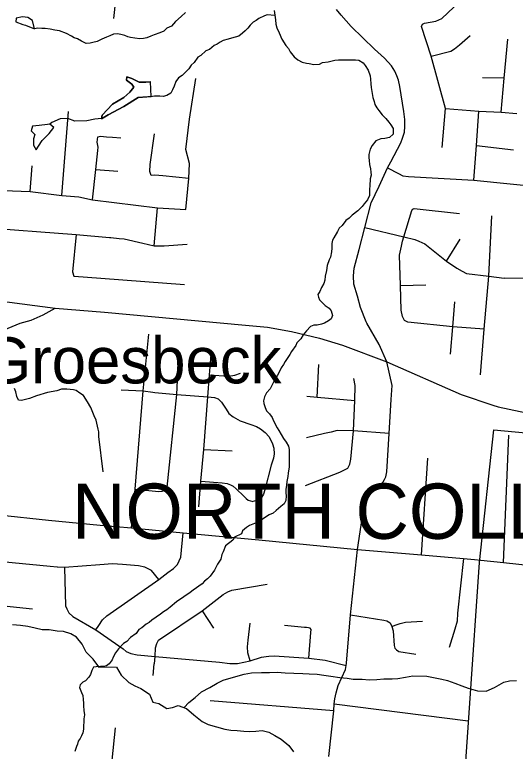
# Model space of a CAD drawing. Extents: x 0 to 34, y 0 to 22.
# Drawn here: x 4.564 to 5.421, y 15.023 to 16.285 of the extents above; entities that cross this region are included whole.
import ezdxf

# ---------------------------------------------------------------- set-up
doc = ezdxf.new("R2010")
doc.units = 0
for name, color, linetype in [('GM_X_City_Street', 7, 'Continuous'), ('GM_X_Corporation', 7, 'Continuous'), ('GM_X_Corporation_Text', 7, 'Continuous'), ('GM_X_County_Road', 7, 'Continuous'), ('GM_X_Minor_Lake', 7, 'Continuous'), ('GM_X_Minor_River', 7, 'Continuous'), ('GM_X_State_Route', 7, 'Continuous'), ('GM_X_Township_Subdivision', 7, 'Continuous'), ('GM_X_Unincorporated_Text', 7, 'Continuous')]:
    doc.layers.add(name, color=color, linetype=linetype)

msp = doc.modelspace()

# ---------------------------------------------------------------- linework, layer by layer
at = {"layer": 'GM_X_City_Street'}
for points in [[(5.4006, 15.3461), (5.41, 15.5645)], [(5.351, 15.3514), (5.3619, 15.3502), (5.4006, 15.3461), (5.5108, 15.3345)]]:
    msp.add_lwpolyline(points, dxfattribs=at)
at = {"layer": 'GM_X_Corporation'}
msp.add_lwpolyline([(5.3269, 14.8644), (5.36, 15.3466), (5.3844, 15.5735), (5.5787, 15.5551), (5.5807, 15.5674), (5.8665, 15.5358), (5.8686, 15.5537), (5.9354, 15.5498), (5.9645, 15.8066), (5.9702, 15.8563), (6.4625, 15.7812), (6.9592, 15.6968), (6.9605, 15.6641), (7.1222, 15.6381)], dxfattribs=at)
at = {"layer": 'GM_X_County_Road'}
for points in [[(5.1657, 15.7589), (5.1559, 15.7831), (5.151, 15.8025), (5.1444, 15.8229), (5.1438, 15.8374), (5.1451, 15.8507), (5.1538, 15.8827), (5.1633, 15.9201), (5.174, 15.9624), (5.1809, 15.977), (5.188, 15.9913), (5.2022, 16.0226), (5.2078, 16.0328), (5.2193, 16.0543), (5.2248, 16.0653), (5.2281, 16.0731), (5.2314, 16.0834), (5.2321, 16.093), (5.2317, 16.1054), (5.2299, 16.1191), (5.2233, 16.1615), (5.2208, 16.1726), (5.2183, 16.1803), (5.215, 16.1881), (5.2089, 16.197), (5.1971, 16.2101), (5.1802, 16.2256), (5.1401, 16.2646), (5.1231, 16.2839), (5.1147, 16.2938)], [(5.2087, 15.6258), (5.2102, 15.6493), (5.201, 15.6901), (5.1882, 15.72), (5.1668, 15.7562), (5.1657, 15.7589)], [(5.1017, 15.0142), (5.1101, 15.0924), (5.1111, 15.1045), (5.1121, 15.113), (5.1142, 15.1228), (5.118, 15.1354), (5.1303, 15.1632), (5.1312, 15.1697), (5.1319, 15.1738), (5.139, 15.2568), (5.1507, 15.3687), (5.1604, 15.4332), (5.1638, 15.4483), (5.1657, 15.4549), (5.1685, 15.46), (5.1713, 15.4638), (5.1744, 15.4669), (5.1856, 15.4753), (5.1903, 15.4797), (5.1949, 15.4845), (5.1972, 15.4886), (5.1991, 15.4932), (5.2012, 15.5016), (5.2049, 15.5671), (5.2087, 15.6258)], [(4.5333, 15.4281), (4.5365, 15.4278), (4.6218, 15.4186), (4.7103, 15.4103), (4.7637, 15.4056), (4.8525, 15.397), (4.9822, 15.3853), (5.1507, 15.3687)], [(5.1507, 15.3687), (5.2604, 15.3597), (5.3321, 15.3534), (5.351, 15.3514)]]:
    msp.add_lwpolyline(points, dxfattribs=at)
at = {"layer": 'GM_X_Minor_Lake'}
for points in [[(4.5981, 16.2605), (4.5946, 16.2751), (4.5863, 16.2802), (4.5773, 16.2812), (4.5662, 16.2788), (4.5657, 16.2724), (4.5781, 16.2679), (4.5826, 16.2667)], [(4.5826, 16.2667), (4.5981, 16.2605)], [(4.7965, 16.1699), (4.7882, 16.169), (4.7772, 16.1693), (4.7644, 16.1756), (4.7558, 16.1785), (4.7556, 16.1728), (4.7646, 16.1658), (4.7679, 16.1604), (4.7612, 16.1522), (4.7508, 16.1429), (4.7315, 16.1316), (4.7136, 16.1126), (4.7127, 16.1065), (4.7239, 16.1131), (4.7508, 16.1277), (4.7751, 16.1431), (4.7978, 16.1446)], [(4.7998, 16.1447), (4.7751, 16.1431), (4.7508, 16.1277), (4.7239, 16.1131), (4.7127, 16.1065), (4.7136, 16.1126), (4.7315, 16.1316), (4.7508, 16.1429), (4.7612, 16.1522), (4.7679, 16.1604), (4.7646, 16.1658), (4.7556, 16.1728), (4.7558, 16.1785), (4.7644, 16.1756), (4.7772, 16.1693), (4.7882, 16.169), (4.797, 16.17)], [(4.7978, 16.1446), (4.7965, 16.1699)], [(4.6199, 16.0964), (4.6061, 16.0948), (4.5947, 16.0936), (4.5923, 16.086), (4.5982, 16.0798), (4.5961, 16.0723), (4.5959, 16.0613), (4.601, 16.0532), (4.6046, 16.0595), (4.6109, 16.0693), (4.6229, 16.0812), (4.6308, 16.0916), (4.624, 16.0971)], [(4.624, 16.0971), (4.6199, 16.0964)]]:
    msp.add_lwpolyline(points, dxfattribs=at)
at = {"layer": 'GM_X_Minor_River'}
for points in [[(5.008, 16.2922), (5.0102, 16.2761), (5.0108, 16.2685), (5.0125, 16.262), (5.0168, 16.2535), (5.0211, 16.2427), (5.028, 16.2318), (5.0329, 16.2271), (5.0357, 16.2213), (5.0427, 16.2128), (5.0487, 16.2076), (5.0562, 16.2036), (5.0633, 16.2015), (5.0683, 16.201), (5.0762, 16.1993), (5.0857, 16.2001), (5.0911, 16.2027), (5.1007, 16.2043), (5.1122, 16.207), (5.1186, 16.2072), (5.1244, 16.2074), (5.1358, 16.2075), (5.1403, 16.2074), (5.1476, 16.2076), (5.1529, 16.207), (5.1607, 16.2022), (5.164, 16.1976), (5.1691, 16.1898), (5.1727, 16.1802), (5.1729, 16.1745), (5.1738, 16.1665), (5.174, 16.16), (5.1757, 16.15), (5.177, 16.1431), (5.1795, 16.1358), (5.1808, 16.1309), (5.1841, 16.125), (5.1874, 16.1204), (5.1929, 16.113), (5.1996, 16.1071), (5.2047, 16.1009), (5.208, 16.0962), (5.2121, 16.09), (5.2118, 16.0801)], [(4.8562, 16.2888), (4.8491, 16.2818), (4.839, 16.2729), (4.8323, 16.2651), (4.8243, 16.2615), (4.8192, 16.2563), (4.8122, 16.2535), (4.8026, 16.2503), (4.7973, 16.2482), (4.7903, 16.2453), (4.7842, 16.244), (4.7781, 16.2437), (4.7694, 16.2444), (4.7622, 16.2457), (4.7577, 16.247), (4.7528, 16.249), (4.7456, 16.2511), (4.7399, 16.2521), (4.7331, 16.2515), (4.7269, 16.2486), (4.7212, 16.2465), (4.7131, 16.2429), (4.705, 16.2389), (4.6977, 16.2369), (4.6931, 16.2362), (4.6866, 16.2356), (4.6784, 16.2397), (4.6713, 16.2433), (4.666, 16.2454), (4.6611, 16.2482), (4.6529, 16.2526), (4.6405, 16.2571), (4.6325, 16.2585), (4.6249, 16.2598), (4.6162, 16.2612), (4.6105, 16.261), (4.6033, 16.2616), (4.5976, 16.2604)], [(5.0092, 16.2832), (4.996, 16.2845), (4.9914, 16.2831), (4.9821, 16.278), (4.9771, 16.2751), (4.9721, 16.2719), (4.967, 16.2667), (4.9631, 16.2618), (4.9584, 16.2574), (4.9541, 16.2529), (4.9479, 16.2482), (4.9413, 16.2461), (4.9352, 16.2443), (4.9295, 16.2426), (4.921, 16.2405), (4.9156, 16.238), (4.9106, 16.2343), (4.9056, 16.2322), (4.8974, 16.2252), (4.8913, 16.2227), (4.8827, 16.2146), (4.8773, 16.212), (4.8713, 16.2027), (4.8659, 16.1983), (4.8623, 16.1923), (4.8572, 16.1867), (4.8506, 16.1804), (4.8444, 16.1768), (4.8397, 16.1704), (4.8368, 16.1621), (4.8339, 16.1558), (4.8311, 16.1505), (4.8242, 16.1465), (4.818, 16.1448), (4.8127, 16.1453), (4.8032, 16.1452), (4.7998, 16.1447)], [(4.7128, 16.1069), (4.7013, 16.106), (4.6876, 16.1029), (4.6667, 16.1022), (4.655, 16.107), (4.6417, 16.1062), (4.6275, 16.1001), (4.624, 16.0971)], [(5.2118, 16.0801), (5.2059, 16.0742), (5.1975, 16.0725), (5.191, 16.0719), (5.1822, 16.0687), (5.1759, 16.0605), (5.1723, 16.0542), (5.1702, 16.0455), (5.17, 16.0401), (5.1706, 16.0348), (5.1716, 16.0283), (5.1729, 16.0206), (5.1735, 16.0153), (5.1745, 16.0096), (5.1724, 16.0035), (5.1721, 15.9917), (5.1712, 15.986), (5.1714, 15.9807), (5.1713, 15.975), (5.168, 15.9678), (5.1625, 15.9608), (5.159, 15.9563), (5.1516, 15.9489), (5.1418, 15.9412), (5.1364, 15.936), (5.131, 15.9323), (5.1246, 15.9234), (5.1196, 15.9189), (5.1164, 15.9133), (5.1104, 15.9028), (5.108, 15.8983), (5.1067, 15.893), (5.1069, 15.885), (5.1063, 15.8786), (5.1045, 15.8695), (5.1021, 15.865), (5.0988, 15.8551), (5.0975, 15.8468), (5.0957, 15.837), (5.0947, 15.8301), (5.093, 15.8241), (5.0894, 15.8173), (5.0866, 15.8106), (5.083, 15.8057), (5.084, 15.8007), (5.0858, 15.7961), (5.091, 15.7914), (5.0954, 15.7867), (5.1026, 15.7823), (5.1055, 15.7777), (5.1079, 15.7696), (5.1059, 15.7639), (5.1012, 15.7606), (5.0946, 15.7566), (5.0892, 15.7545), (5.082, 15.7532), (5.0763, 15.753), (5.0705, 15.7508), (5.0635, 15.743), (5.0576, 15.7363), (5.0536, 15.7296), (5.0469, 15.7226), (5.0453, 15.718), (5.0378, 15.708), (5.035, 15.7027), (5.0271, 15.6907), (5.0239, 15.6855), (5.0199, 15.6799), (5.0175, 15.6735), (5.0139, 15.6671), (5.0107, 15.6619), (5.0063, 15.6544), (5.0043, 15.6495), (5.0011, 15.6439), (4.9952, 15.6368), (4.9916, 15.6304), (4.9902, 15.6232), (4.9905, 15.6186), (4.993, 15.6117), (4.9951, 15.606), (5.0003, 15.6012), (5.0047, 15.595), (5.0068, 15.5889), (5.0133, 15.5773), (5.0159, 15.5722), (5.0199, 15.5657), (5.0242, 15.5587), (5.029, 15.5525), (5.033, 15.5459), (5.034, 15.5398), (5.0341, 15.5306), (5.0336, 15.5101), (5.0321, 15.4994), (5.0316, 15.4934), (5.0298, 15.485), (5.0293, 15.4786), (5.0283, 15.4714), (5.0282, 15.4657), (5.0288, 15.4603), (5.0282, 15.4527), (5.0254, 15.4471)], [(4.7154, 15.5018), (4.7079, 15.5622), (4.7078, 15.5702), (4.7071, 15.5748), (4.7034, 15.5901), (4.7001, 15.5978), (4.6941, 15.6117), (4.6886, 15.6217), (4.6817, 15.6322), (4.6753, 15.6366), (4.6694, 15.6409), (4.6645, 15.6422), (4.6531, 15.6433), (4.6443, 15.6431), (4.6359, 15.6407), (4.6202, 15.6377), (4.6014, 15.6318), (4.5891, 15.6272), (4.5754, 15.6241), (4.5704, 15.6246), (4.5679, 15.6308), (4.5659, 15.6389), (4.5634, 15.6446)], [(5.0254, 15.4471), (5.0196, 15.4423), (5.0114, 15.4357), (5.0063, 15.4309), (4.9994, 15.428), (4.9866, 15.4192), (4.9804, 15.4156), (4.9658, 15.4095), (4.9608, 15.4062), (4.9542, 15.4007), (4.9521, 15.3954), (4.9405, 15.3897), (4.9377, 15.3844), (4.9246, 15.3749), (4.9209, 15.3647), (4.9188, 15.3598), (4.9167, 15.3522), (4.9112, 15.3436), (4.9059, 15.3335), (4.8988, 15.3227), (4.8941, 15.3182), (4.8891, 15.3142), (4.8848, 15.3097), (4.8693, 15.2987), (4.8642, 15.2951), (4.8534, 15.2878), (4.841, 15.279), (4.8304, 15.2697), (4.8242, 15.265), (4.8188, 15.2617), (4.8134, 15.258), (4.806, 15.2529), (4.799, 15.2478), (4.794, 15.2437), (4.789, 15.2408), (4.7816, 15.2342), (4.7765, 15.2313), (4.7722, 15.2249), (4.7621, 15.2179), (4.7562, 15.2109), (4.7504, 15.2076), (4.7414, 15.1983), (4.7367, 15.1916), (4.7327, 15.1841), (4.731, 15.1796), (4.7255, 15.1725), (4.7209, 15.1696), (4.7159, 15.1682), (4.7109, 15.168), (4.7037, 15.1678), (4.6991, 15.1672), (4.6963, 15.1615), (4.6935, 15.1547), (4.6907, 15.1499), (4.6852, 15.1439), (4.6805, 15.1414), (4.6762, 15.1366), (4.675, 15.132), (4.6785, 15.1239), (4.6807, 15.1185), (4.6813, 15.1117), (4.6815, 15.1056), (4.6817, 15.101), (4.6826, 15.0926), (4.6832, 15.0853), (4.6826, 15.0785), (4.6825, 15.0732), (4.6819, 15.0667), (4.6818, 15.0606), (4.6805, 15.0546), (4.6781, 15.0497), (4.676, 15.0448), (4.6729, 15.0403), (4.6712, 15.0354), (4.6696, 15.0309), (4.6667, 15.0226)], [(4.708, 15.1679), (4.6985, 15.181), (4.6862, 15.1927), (4.6797, 15.2062), (4.6697, 15.2186), (4.66, 15.2242), (4.6475, 15.2279), (4.6369, 15.2285), (4.6229, 15.2308), (4.6111, 15.2311), (4.599, 15.234), (4.5862, 15.2366), (4.5741, 15.2384), (4.5604, 15.2395)], [(4.7066, 15.1679), (4.738, 15.1671), (4.746, 15.1536), (4.7594, 15.1408), (4.7695, 15.1348), (4.7797, 15.1304), (4.795, 15.1209), (4.8004, 15.1071), (4.8106, 15.1049), (4.8245, 15.0962), (4.8344, 15.0979), (4.844, 15.1014), (4.8579, 15.0965), (4.8709, 15.0852), (4.8851, 15.0742), (4.8952, 15.069), (4.9239, 15.0611), (4.9341, 15.0593), (4.9451, 15.0587), (4.9565, 15.0572), (4.9664, 15.0566), (4.9767, 15.0575), (4.9877, 15.0584), (4.999, 15.0558), (5.0095, 15.0502), (5.02, 15.0435), (5.0331, 15.0326), (5.0415, 15.0221)], [(4.8543, 15.0978), (4.8619, 15.1063), (4.8732, 15.1152), (4.8837, 15.1248), (4.8983, 15.1324), (4.9106, 15.1397), (4.921, 15.1448), (4.9425, 15.1511), (4.9566, 15.155), (4.9696, 15.1573), (4.9867, 15.1581), (5.0004, 15.1577), (5.0133, 15.1585), (5.0273, 15.1574), (5.0421, 15.1567), (5.0573, 15.156), (5.0683, 15.1557), (5.0816, 15.155), (5.093, 15.1536), (5.1051, 15.1514), (5.1206, 15.1491), (5.1331, 15.148), (5.1434, 15.1466), (5.1589, 15.1463), (5.1711, 15.1456), (5.184, 15.146), (5.1962, 15.1469), (5.2103, 15.1473), (5.2198, 15.1478), (5.2328, 15.1502), (5.2457, 15.1521), (5.2693, 15.1516), (5.281, 15.1494), (5.295, 15.1464), (5.3052, 15.1442), (5.3176, 15.1397), (5.3293, 15.1349), (5.3406, 15.1312), (5.3564, 15.1266), (5.3709, 15.1259), (5.3855, 15.1324), (5.4013, 15.1415), (5.4108, 15.1439), (5.423, 15.144)]]:
    msp.add_lwpolyline(points, dxfattribs=at)
at = {"layer": 'GM_X_State_Route'}
for points in [[(4.4326, 15.8115), (4.5051, 15.799), (4.5196, 15.797), (4.6332, 15.782)], [(4.3903, 15.6863), (4.4453, 15.699), (4.4698, 15.7077), (4.4911, 15.7177), (4.5331, 15.7387), (4.5528, 15.7478), (4.5732, 15.7562), (4.5922, 15.7616), (4.6126, 15.7705), (4.6332, 15.782)], [(4.6332, 15.782), (4.7176, 15.7753), (4.959, 15.7532), (4.9968, 15.7493), (5.0379, 15.742), (5.0859, 15.7305), (5.1254, 15.7187), (5.201, 15.6901), (5.3286, 15.6339), (5.3828, 15.616), (5.3914, 15.6131), (5.4588, 15.599), (5.5268, 15.5892), (5.7096, 15.5717), (5.7429, 15.5711), (5.7725, 15.5744), (5.8001, 15.5813), (5.8247, 15.5928), (5.8445, 15.6036), (5.8718, 15.6263), (5.8997, 15.6575), (5.9497, 15.7302), (5.9627, 15.7461)]]:
    msp.add_lwpolyline(points, dxfattribs=at)
at = {"layer": 'GM_X_Township_Subdivision'}
for points in [[(4.7335, 16.278), (4.7372, 16.3095), (4.7465, 16.387)], [(5.2956, 16.057), (5.3014, 16.1243), (5.2767, 16.2135), (5.2607, 16.2646), (5.2621, 16.2684), (5.2658, 16.27), (5.2851, 16.2738), (5.2954, 16.2784), (5.3055, 16.2881), (5.3257, 16.3069)], [(5.5577, 16.2722), (5.6156, 16.2678), (5.6217, 16.2658), (5.6252, 16.2617), (5.6075, 16.0089), (5.5945, 15.8445), (5.5933, 15.8347), (5.5895, 15.8274), (5.5833, 15.8204), (5.5783, 15.8191), (5.5702, 15.819), (5.5594, 15.8204), (5.4401, 15.8331), (5.4019, 15.8337)], [(5.2767, 16.2135), (5.3107, 16.2222), (5.317, 16.2264), (5.3254, 16.2333), (5.3436, 16.2491)], [(5.3968, 16.1177), (5.4022, 16.1762), (5.4084, 16.243)], [(5.4022, 16.1762), (5.3646, 16.1768)], [(4.8567, 15.951), (4.8622, 16.004), (4.8634, 16.0296), (4.8572, 16.0536), (4.8634, 16.106), (4.8743, 16.1755)], [(4.6449, 15.9751), (4.6558, 16.1187)], [(5.3014, 16.1243), (5.3583, 16.1195), (5.3968, 16.1177), (5.4234, 16.1157)], [(5.3503, 16.0011), (5.3548, 16.0609), (5.3583, 16.1195)], [(4.4944, 16.1096), (4.4885, 16.0787), (4.4881, 16.0683), (4.488, 16.0579), (4.492, 16.0491), (4.498, 16.0426), (4.5111, 16.0246), (4.5119, 16.014), (4.5111, 15.9993), (4.5088, 15.9773), (4.4992, 15.9245), (4.4999, 15.9222), (4.5025, 15.9206), (4.669, 15.9083), (4.7263, 15.9033)], [(4.6969, 15.9679), (4.7026, 16.0195), (4.7061, 16.052), (4.7067, 16.0578), (4.7052, 16.0665), (4.7062, 16.0756), (4.7111, 16.0766), (4.7212, 16.0753), (4.7315, 16.075), (4.7454, 16.074)], [(4.8622, 16.004), (4.8177, 16.0087), (4.804, 16.0097), (4.7976, 16.0092), (4.7953, 16.0159), (4.796, 16.028), (4.8033, 16.0807)], [(5.3548, 16.0609), (5.418, 16.0532)], [(4.5904, 15.982), (4.5938, 16.0261)], [(4.7026, 16.0195), (4.7408, 16.0167)], [(5.2022, 16.0226), (5.2212, 16.0128), (5.2287, 16.009), (5.2384, 16.0078), (5.3503, 16.0011), (5.4124, 15.9948)], [(5.4124, 15.9948), (5.4518, 15.9911)], [(4.5055, 15.9776), (4.5088, 15.9773), (4.5235, 15.9786), (4.545, 15.9838), (4.5904, 15.982), (4.6449, 15.9751), (4.6518, 15.9745)], [(4.6518, 15.9745), (4.6737, 15.9725), (4.6969, 15.9679), (4.8084, 15.954), (4.8567, 15.951)], [(4.803, 15.8886), (4.8084, 15.954)], [(5.3679, 15.7459), (5.3141, 15.7503), (5.2368, 15.758), (5.2316, 15.7612), (5.228, 15.7677), (5.2256, 15.7784), (5.2244, 15.8207), (5.2228, 15.8726), (5.2264, 15.8882), (5.2278, 15.8969), (5.2301, 15.9044), (5.2439, 15.9493), (5.2455, 15.9519), (5.2478, 15.953), (5.3254, 15.9442)], [(5.3614, 15.668), (5.3679, 15.7459), (5.3757, 15.8369), (5.3811, 15.9405)], [(5.1633, 15.9201), (5.2301, 15.9044), (5.249, 15.8995), (5.256, 15.8968), (5.2659, 15.8924), (5.3035, 15.8628), (5.3208, 15.8504), (5.3298, 15.8452), (5.3372, 15.8417), (5.3757, 15.8369), (5.4019, 15.8337)], [(4.669, 15.9083), (4.6631, 15.844), (4.6654, 15.8367), (4.6814, 15.8355), (4.8549, 15.8225)], [(4.7263, 15.9033), (4.7286, 15.9031), (4.7428, 15.9013), (4.7514, 15.901), (4.7831, 15.8934)], [(5.3035, 15.8628), (5.3269, 15.9001)], [(4.7831, 15.8934), (4.803, 15.8886), (4.8198, 15.8886), (4.8595, 15.8917)], [(5.2244, 15.8207), (5.268, 15.8219)], [(5.3101, 15.7032), (5.3141, 15.7503), (5.3176, 15.7929)], [(4.7637, 15.4056), (4.7701, 15.4718), (4.7838, 15.6402), (4.7935, 15.7375)], [(4.7701, 15.4718), (4.8108, 15.4678), (4.8166, 15.4686), (4.8212, 15.4705), (4.8251, 15.4754), (4.8413, 15.6341), (4.8451, 15.7081)], [(4.879, 15.4417), (4.8829, 15.4855), (4.8877, 15.5399), (4.8945, 15.6303), (4.8977, 15.6679), (4.9005, 15.7022)], [(5.0819, 15.6297), (5.0848, 15.6857)], [(4.8977, 15.6679), (4.9301, 15.6654), (4.9408, 15.6675), (4.9504, 15.6706)], [(5.0621, 15.4782), (5.1207, 15.5011), (5.1344, 15.508), (5.1378, 15.5149), (5.1394, 15.5234), (5.1442, 15.5721), (5.1465, 15.6237), (5.147, 15.6497), (5.1444, 15.6616)], [(4.746, 15.6422), (4.7838, 15.6402), (4.8005, 15.6382)], [(4.8005, 15.6382), (4.8036, 15.6378), (4.8413, 15.6341), (4.8945, 15.6303), (4.9061, 15.6289), (4.9121, 15.6265), (4.918, 15.6209), (4.9261, 15.6088), (4.9304, 15.6017), (4.9382, 15.5957), (4.9497, 15.5892), (4.9685, 15.5827), (4.9781, 15.5791), (4.9846, 15.5753), (4.9927, 15.5688), (4.9994, 15.5616), (5.0055, 15.5499), (5.0076, 15.5422), (5.0081, 15.5326), (5.007, 15.5251), (5.0032, 15.5129), (4.992, 15.4708), (4.9897, 15.4636), (4.9864, 15.4578), (4.9836, 15.455), (4.98, 15.4531), (4.9718, 15.451)], [(5.064, 15.6311), (5.0819, 15.6297), (5.1465, 15.6237)], [(5.2049, 15.5671), (5.1442, 15.5721), (5.1161, 15.5722), (5.1058, 15.5698), (5.0943, 15.5674), (5.0634, 15.5598)], [(4.8877, 15.5399), (4.9365, 15.5379)], [(5.2604, 15.3597), (5.2711, 15.525)], [(4.8829, 15.4855), (4.9192, 15.4828), (4.9279, 15.4816), (4.9337, 15.4793), (4.9379, 15.4772), (4.9431, 15.4728), (4.956, 15.46), (4.9601, 15.4558), (4.9636, 15.4531), (4.9718, 15.451)], [(4.7028, 15.231), (4.7081, 15.2386), (4.7142, 15.2484), (4.7215, 15.2551), (4.8106, 15.3175), (4.8264, 15.3291), (4.8359, 15.3361), (4.8429, 15.3431), (4.8484, 15.3554), (4.8525, 15.397)], [(4.6365, 15.3382), (4.6244, 15.3396), (4.4644, 15.355)], [(4.8106, 15.3175), (4.7979, 15.3328), (4.7866, 15.3382), (4.7758, 15.3404), (4.7488, 15.3429), (4.7313, 15.3443), (4.7097, 15.3426), (4.6494, 15.3377), (4.6374, 15.3381), (4.6365, 15.3382)], [(5.3321, 15.3534), (5.3222, 15.2597), (5.3213, 15.2457), (5.3174, 15.2324), (5.3079, 15.201)], [(4.6494, 15.3377), (4.6509, 15.2723), (4.6531, 15.2669), (4.6567, 15.2604), (4.6637, 15.2541), (4.7028, 15.231), (4.7494, 15.1983), (4.755, 15.1941), (4.7627, 15.1906), (4.7738, 15.188), (4.8043, 15.1851), (4.9146, 15.1755), (4.9325, 15.1732), (4.9455, 15.1731), (4.9673, 15.1781), (4.9866, 15.1844), (4.9943, 15.1854), (4.999, 15.1857), (5.008, 15.1864), (5.0675, 15.1827), (5.0957, 15.1791), (5.1312, 15.1697)], [(4.8031, 15.173), (4.8043, 15.1851), (4.8053, 15.2), (4.8072, 15.2077), (4.8103, 15.2131), (4.8847, 15.2637), (4.921, 15.2916), (4.9291, 15.2962), (4.9356, 15.299), (4.9964, 15.3093)], [(4.4752, 15.2718), (4.5061, 15.2736), (4.523, 15.2745), (4.5946, 15.2672)], [(4.8847, 15.2637), (4.9044, 15.2339)], [(5.139, 15.2568), (5.1959, 15.2478), (5.2008, 15.2465), (5.2065, 15.2429), (5.2099, 15.2369), (5.2122, 15.2295), (5.2134, 15.204), (5.2145, 15.1994), (5.2174, 15.1967), (5.2219, 15.1939), (5.2506, 15.1894)], [(4.9673, 15.1781), (4.9631, 15.1914), (4.9625, 15.2019), (4.9636, 15.2131), (4.9671, 15.2427)], [(5.2099, 15.2369), (5.2173, 15.2397), (5.2239, 15.2421), (5.2332, 15.2442), (5.2619, 15.2461)], [(5.0675, 15.1827), (5.071, 15.2262), (5.0714, 15.2317), (5.0697, 15.2336), (5.0667, 15.2346), (5.0636, 15.235), (5.0599, 15.235), (5.0256, 15.2382)], [(4.8008, 15.1527), (4.803, 15.1726), (4.8031, 15.173)], [(5.1101, 15.0924), (4.8984, 15.1092)], [(5.1111, 15.1045), (5.3404, 15.0752)], [(4.7213, 14.9134), (4.7368, 15.0634)]]:
    msp.add_lwpolyline(points, dxfattribs=at)

# ---------------------------------------------------------------- texts
at = {"layer": 'GM_X_Corporation_Text'}
msp.add_text('NORTH COLLEGE HILL', height=0.094697, rotation=0, dxfattribs=at).set_placement((4.662, 15.3869))
at = {"layer": 'GM_X_Unincorporated_Text'}
msp.add_text('Groesbeck', height=0.07898, rotation=0, dxfattribs=at).set_placement((4.51, 15.6532))

doc.saveas('drawing.dxf')
